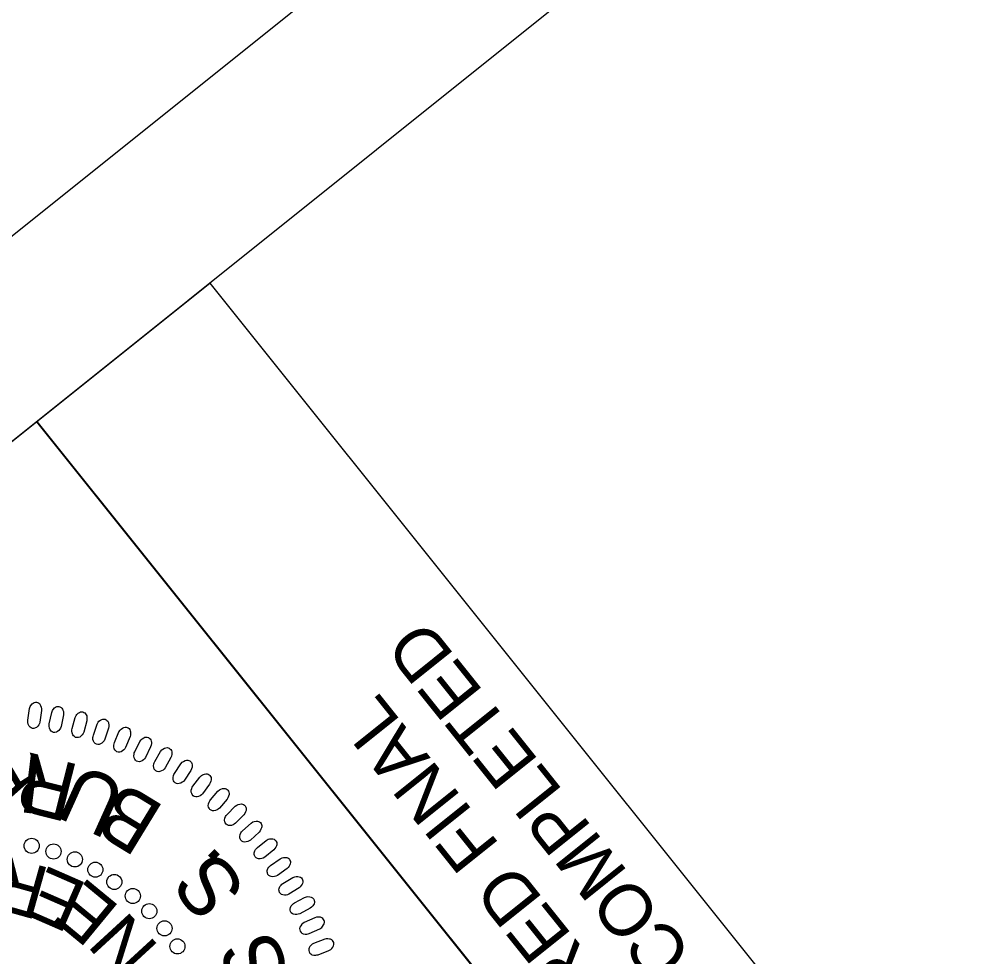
# Model space of a CAD drawing. Extents: x 473437 to 475344, y 504319 to 506318.
# Drawn here: x 473580.9 to 473682.6, y 505671.2 to 505770.6 of the extents above; entities that cross this region are included whole.
import ezdxf

# ---------------------------------------------------------------- set-up
doc = ezdxf.new("R2010")
doc.units = 0
for name, color, linetype in [('Sheet PE Seal Cell', 7, 'Continuous'), ('Sheet Plan CELL', 7, 'Continuous'), ('Sheet Plot Border Outside CELL', 7, 'Continuous'), ('Sheet Sticker Exception Certification CELL', 7, 'Continuous'), ('Sheet Sticker Incomplete CELL', 7, 'Continuous')]:
    doc.layers.add(name, color=color, linetype=linetype)

msp = doc.modelspace()

# ---------------------------------------------------------------- linework, layer by layer
at = {"layer": 'Sheet PE Seal Cell'}
for points in [[(473581.77, 505696.29), (473581.95, 505697.5), (473582.02, 505697.71), (473582.09, 505697.84), (473582.22, 505698), (473582.33, 505698.09), (473582.46, 505698.15), (473582.57, 505698.18), (473582.68, 505698.18), (473582.79, 505698.15), (473582.9, 505698.1), (473583, 505698.03), (473583.09, 505697.91), (473583.13, 505697.82), (473583.18, 505697.67), (473583.21, 505697.48), (473583.21, 505697.32), (473583.04, 505696.07), (473583, 505695.91), (473582.93, 505695.78), (473582.82, 505695.63), (473582.69, 505695.51), (473582.58, 505695.45), (473582.42, 505695.41), (473582.27, 505695.41), (473582.13, 505695.47), (473582.03, 505695.54), (473581.92, 505695.65), (473581.82, 505695.84), (473581.78, 505696.02), (473581.77, 505696.16)], [(473584.05, 505695.89), (473584.3, 505697.09), (473584.38, 505697.3), (473584.46, 505697.42), (473584.6, 505697.57), (473584.72, 505697.65), (473584.85, 505697.71), (473584.96, 505697.73), (473585.07, 505697.72), (473585.18, 505697.68), (473585.29, 505697.63), (473585.38, 505697.55), (473585.46, 505697.43), (473585.5, 505697.34), (473585.54, 505697.18), (473585.56, 505696.99), (473585.55, 505696.83), (473585.3, 505695.6), (473585.25, 505695.44), (473585.17, 505695.31), (473585.05, 505695.17), (473584.92, 505695.06), (473584.8, 505695), (473584.64, 505694.97), (473584.49, 505694.98), (473584.35, 505695.05), (473584.26, 505695.12), (473584.15, 505695.25), (473584.07, 505695.44), (473584.04, 505695.63), (473584.04, 505695.76)], [(473586.46, 505695.38), (473586.79, 505696.56), (473586.88, 505696.76), (473586.97, 505696.89), (473587.12, 505697.02), (473587.25, 505697.1), (473587.37, 505697.15), (473587.49, 505697.16), (473587.6, 505697.15), (473587.7, 505697.1), (473587.81, 505697.04), (473587.9, 505696.95), (473587.97, 505696.83), (473588.01, 505696.73), (473588.03, 505696.57), (473588.04, 505696.38), (473588.02, 505696.22), (473587.7, 505695.01), (473587.63, 505694.85), (473587.55, 505694.73), (473587.42, 505694.6), (473587.28, 505694.49), (473587.16, 505694.44), (473586.99, 505694.43), (473586.84, 505694.45), (473586.71, 505694.53), (473586.62, 505694.6), (473586.53, 505694.73), (473586.46, 505694.93), (473586.44, 505695.12), (473586.44, 505695.25)], [(473588.72, 505694.69), (473589.11, 505695.85), (473589.22, 505696.05), (473589.31, 505696.16), (473589.48, 505696.29), (473589.6, 505696.36), (473589.74, 505696.4), (473589.85, 505696.4), (473589.96, 505696.38), (473590.06, 505696.33), (473590.16, 505696.26), (473590.24, 505696.17), (473590.31, 505696.04), (473590.34, 505695.95), (473590.36, 505695.78), (473590.35, 505695.59), (473590.32, 505695.44), (473589.92, 505694.25), (473589.85, 505694.09), (473589.76, 505693.98), (473589.62, 505693.85), (473589.47, 505693.76), (473589.35, 505693.71), (473589.18, 505693.71), (473589.04, 505693.74), (473588.91, 505693.82), (473588.82, 505693.91), (473588.74, 505694.04), (473588.68, 505694.24), (473588.67, 505694.43), (473588.69, 505694.56)], [(473590.96, 505693.9), (473591.43, 505695.03), (473591.55, 505695.22), (473591.65, 505695.33), (473591.82, 505695.44), (473591.95, 505695.51), (473592.08, 505695.54), (473592.19, 505695.54), (473592.31, 505695.51), (473592.4, 505695.45), (473592.5, 505695.38), (473592.57, 505695.28), (473592.63, 505695.15), (473592.66, 505695.05), (473592.66, 505694.89), (473592.65, 505694.7), (473592.61, 505694.54), (473592.13, 505693.38), (473592.05, 505693.23), (473591.95, 505693.12), (473591.81, 505693.01), (473591.65, 505692.92), (473591.53, 505692.88), (473591.36, 505692.89), (473591.22, 505692.93), (473591.1, 505693.02), (473591.02, 505693.11), (473590.94, 505693.25), (473590.89, 505693.45), (473590.9, 505693.64), (473590.92, 505693.78)], [(473593.1, 505692.92), (473593.64, 505694.03), (473593.77, 505694.21), (473593.88, 505694.31), (473594.06, 505694.41), (473594.19, 505694.47), (473594.33, 505694.49), (473594.44, 505694.48), (473594.55, 505694.45), (473594.64, 505694.38), (473594.73, 505694.3), (473594.8, 505694.2), (473594.85, 505694.06), (473594.87, 505693.97), (473594.87, 505693.8), (473594.84, 505693.62), (473594.79, 505693.46), (473594.24, 505692.33), (473594.15, 505692.19), (473594.05, 505692.08), (473593.89, 505691.98), (473593.73, 505691.9), (473593.61, 505691.87), (473593.44, 505691.89), (473593.3, 505691.94), (473593.18, 505692.04), (473593.11, 505692.13), (473593.04, 505692.28), (473593.01, 505692.48), (473593.03, 505692.67), (473593.06, 505692.8)], [(473595.22, 505691.89), (473595.83, 505692.96), (473595.97, 505693.13), (473596.08, 505693.22), (473596.26, 505693.32), (473596.4, 505693.36), (473596.54, 505693.38), (473596.65, 505693.36), (473596.76, 505693.32), (473596.84, 505693.25), (473596.93, 505693.16), (473596.99, 505693.06), (473597.04, 505692.92), (473597.05, 505692.82), (473597.03, 505692.66), (473596.99, 505692.47), (473596.94, 505692.32), (473596.32, 505691.23), (473596.21, 505691.09), (473596.11, 505690.99), (473595.95, 505690.9), (473595.78, 505690.83), (473595.66, 505690.81), (473595.49, 505690.84), (473595.35, 505690.9), (473595.24, 505691), (473595.18, 505691.1), (473595.12, 505691.25), (473595.1, 505691.45), (473595.13, 505691.65), (473595.17, 505691.77)], [(473597.32, 505690.64), (473597.99, 505691.66), (473598.15, 505691.83), (473598.27, 505691.91), (473598.45, 505691.99), (473598.59, 505692.03), (473598.73, 505692.04), (473598.84, 505692.01), (473598.95, 505691.97), (473599.03, 505691.89), (473599.11, 505691.8), (473599.17, 505691.69), (473599.2, 505691.55), (473599.21, 505691.45), (473599.18, 505691.29), (473599.13, 505691.11), (473599.06, 505690.96), (473598.38, 505689.91), (473598.27, 505689.78), (473598.15, 505689.69), (473597.99, 505689.6), (473597.82, 505689.55), (473597.69, 505689.53), (473597.53, 505689.57), (473597.39, 505689.64), (473597.29, 505689.75), (473597.23, 505689.85), (473597.18, 505690), (473597.17, 505690.21), (473597.22, 505690.4), (473597.26, 505690.52)], [(473599.28, 505689.27), (473600.01, 505690.25), (473600.18, 505690.4), (473600.3, 505690.48), (473600.49, 505690.55), (473600.64, 505690.58), (473600.77, 505690.58), (473600.88, 505690.55), (473600.98, 505690.49), (473601.06, 505690.41), (473601.14, 505690.31), (473601.19, 505690.2), (473601.21, 505690.06), (473601.21, 505689.96), (473601.17, 505689.8), (473601.11, 505689.62), (473601.04, 505689.48), (473600.29, 505688.47), (473600.17, 505688.35), (473600.05, 505688.27), (473599.88, 505688.19), (473599.71, 505688.15), (473599.58, 505688.14), (473599.42, 505688.19), (473599.29, 505688.26), (473599.19, 505688.39), (473599.14, 505688.49), (473599.1, 505688.64), (473599.1, 505688.85), (473599.16, 505689.04), (473599.21, 505689.16)], [(473601.12, 505687.82), (473601.92, 505688.75), (473602.09, 505688.9), (473602.22, 505688.97), (473602.42, 505689.02), (473602.56, 505689.04), (473602.7, 505689.03), (473602.81, 505688.99), (473602.9, 505688.94), (473602.98, 505688.85), (473603.05, 505688.75), (473603.09, 505688.63), (473603.1, 505688.49), (473603.1, 505688.39), (473603.05, 505688.23), (473602.98, 505688.06), (473602.89, 505687.92), (473602.08, 505686.96), (473601.96, 505686.85), (473601.83, 505686.77), (473601.66, 505686.71), (473601.48, 505686.67), (473601.36, 505686.68), (473601.2, 505686.73), (473601.07, 505686.82), (473600.98, 505686.94), (473600.94, 505687.05), (473600.9, 505687.21), (473600.92, 505687.41), (473600.99, 505687.6), (473601.05, 505687.71)], [(473602.89, 505686.27), (473603.75, 505687.15), (473603.93, 505687.28), (473604.06, 505687.35), (473604.26, 505687.39), (473604.41, 505687.4), (473604.54, 505687.38), (473604.64, 505687.33), (473604.74, 505687.27), (473604.8, 505687.18), (473604.87, 505687.07), (473604.9, 505686.96), (473604.91, 505686.81), (473604.9, 505686.71), (473604.84, 505686.56), (473604.76, 505686.39), (473604.66, 505686.26), (473603.79, 505685.35), (473603.66, 505685.25), (473603.53, 505685.18), (473603.35, 505685.13), (473603.18, 505685.1), (473603.05, 505685.11), (473602.9, 505685.18), (473602.78, 505685.27), (473602.7, 505685.4), (473602.66, 505685.51), (473602.63, 505685.67), (473602.67, 505685.88), (473602.74, 505686.05), (473602.81, 505686.17)], [(473604.52, 505684.54), (473605.43, 505685.37), (473605.62, 505685.49), (473605.75, 505685.54), (473605.96, 505685.58), (473606.1, 505685.58), (473606.24, 505685.55), (473606.34, 505685.5), (473606.43, 505685.43), (473606.49, 505685.33), (473606.55, 505685.22), (473606.57, 505685.1), (473606.57, 505684.96), (473606.55, 505684.86), (473606.48, 505684.71), (473606.39, 505684.55), (473606.29, 505684.42), (473605.36, 505683.57), (473605.22, 505683.47), (473605.09, 505683.41), (473604.91, 505683.37), (473604.73, 505683.36), (473604.61, 505683.38), (473604.46, 505683.46), (473604.34, 505683.55), (473604.27, 505683.69), (473604.24, 505683.8), (473604.23, 505683.96), (473604.27, 505684.17), (473604.36, 505684.34), (473604.43, 505684.45)], [(473606.1, 505682.77), (473607.05, 505683.54), (473607.25, 505683.65), (473607.39, 505683.69), (473607.59, 505683.71), (473607.74, 505683.7), (473607.87, 505683.67), (473607.97, 505683.61), (473608.05, 505683.53), (473608.11, 505683.43), (473608.16, 505683.32), (473608.18, 505683.2), (473608.17, 505683.06), (473608.14, 505682.96), (473608.07, 505682.82), (473607.96, 505682.66), (473607.85, 505682.54), (473606.88, 505681.75), (473606.73, 505681.66), (473606.59, 505681.61), (473606.41, 505681.58), (473606.23, 505681.58), (473606.11, 505681.61), (473605.96, 505681.69), (473605.86, 505681.8), (473605.79, 505681.94), (473605.77, 505682.05), (473605.76, 505682.21), (473605.82, 505682.41), (473605.92, 505682.58), (473606, 505682.68)], [(473607.51, 505680.89), (473608.51, 505681.59), (473608.72, 505681.69), (473608.86, 505681.73), (473609.06, 505681.73), (473609.21, 505681.72), (473609.34, 505681.67), (473609.43, 505681.61), (473609.51, 505681.53), (473609.56, 505681.42), (473609.6, 505681.31), (473609.62, 505681.19), (473609.59, 505681.05), (473609.56, 505680.95), (473609.48, 505680.81), (473609.37, 505680.66), (473609.25, 505680.55), (473608.22, 505679.82), (473608.07, 505679.74), (473607.93, 505679.7), (473607.75, 505679.68), (473607.57, 505679.69), (473607.45, 505679.73), (473607.31, 505679.82), (473607.21, 505679.93), (473607.16, 505680.08), (473607.14, 505680.19), (473607.15, 505680.35), (473607.22, 505680.55), (473607.32, 505680.71), (473607.41, 505680.8)], [(473608.8, 505678.96), (473609.85, 505679.6), (473610.06, 505679.68), (473610.2, 505679.71), (473610.41, 505679.7), (473610.55, 505679.68), (473610.68, 505679.62), (473610.77, 505679.55), (473610.84, 505679.47), (473610.88, 505679.36), (473610.92, 505679.24), (473610.92, 505679.12), (473610.89, 505678.98), (473610.86, 505678.89), (473610.76, 505678.75), (473610.64, 505678.61), (473610.52, 505678.51), (473609.45, 505677.85), (473609.29, 505677.78), (473609.15, 505677.74), (473608.97, 505677.73), (473608.79, 505677.76), (473608.67, 505677.8), (473608.54, 505677.9), (473608.44, 505678.02), (473608.4, 505678.17), (473608.39, 505678.28), (473608.41, 505678.44), (473608.49, 505678.63), (473608.61, 505678.78), (473608.7, 505678.88)], [(473610.03, 505676.91), (473611.11, 505677.48), (473611.32, 505677.55), (473611.47, 505677.57), (473611.67, 505677.55), (473611.82, 505677.51), (473611.94, 505677.45), (473612.02, 505677.38), (473612.09, 505677.29), (473612.13, 505677.18), (473612.16, 505677.06), (473612.15, 505676.94), (473612.11, 505676.8), (473612.07, 505676.71), (473611.97, 505676.58), (473611.84, 505676.44), (473611.71, 505676.35), (473610.6, 505675.76), (473610.44, 505675.7), (473610.3, 505675.67), (473610.11, 505675.68), (473609.94, 505675.71), (473609.82, 505675.76), (473609.7, 505675.87), (473609.61, 505675.99), (473609.57, 505676.14), (473609.57, 505676.26), (473609.6, 505676.42), (473609.69, 505676.6), (473609.82, 505676.75), (473609.92, 505676.83)], [(473611.61, 505673.66), (473612.73, 505674.17), (473612.92, 505674.29), (473613.02, 505674.4), (473613.13, 505674.57), (473613.19, 505674.7), (473613.22, 505674.84), (473613.21, 505674.95), (473613.18, 505675.06), (473613.12, 505675.15), (473613.04, 505675.25), (473612.95, 505675.32), (473612.81, 505675.38), (473612.71, 505675.4), (473612.55, 505675.4), (473612.36, 505675.38), (473612.21, 505675.33), (473611.06, 505674.82), (473610.91, 505674.73), (473610.8, 505674.64), (473610.7, 505674.49), (473610.61, 505674.33), (473610.58, 505674.21), (473610.59, 505674.04), (473610.63, 505673.9), (473610.73, 505673.78), (473610.82, 505673.7), (473610.96, 505673.63), (473611.17, 505673.59), (473611.36, 505673.6), (473611.49, 505673.62)], [(473612.55, 505671.42), (473613.69, 505671.86), (473613.89, 505671.97), (473614, 505672.07), (473614.12, 505672.23), (473614.19, 505672.36), (473614.22, 505672.49), (473614.22, 505672.6), (473614.2, 505672.72), (473614.14, 505672.81), (473614.07, 505672.92), (473613.98, 505672.99), (473613.85, 505673.06), (473613.75, 505673.08), (473613.59, 505673.09), (473613.4, 505673.09), (473613.24, 505673.05), (473612.06, 505672.62), (473611.91, 505672.53), (473611.8, 505672.44), (473611.68, 505672.3), (473611.59, 505672.15), (473611.55, 505672.03), (473611.55, 505671.86), (473611.58, 505671.71), (473611.67, 505671.59), (473611.76, 505671.51), (473611.89, 505671.42), (473612.1, 505671.37), (473612.29, 505671.37), (473612.42, 505671.39)]]:
    msp.add_lwpolyline(points, close=True, dxfattribs=at)
for centre in [(473582.18, 505682.96), (473584.5, 505682.36), (473586.76, 505681.52), (473588.93, 505680.43), (473590.94, 505679.13), (473592.9, 505677.64), (473594.65, 505676.03), (473596.26, 505674.21), (473597.63, 505672.3)]:
    msp.add_circle(centre, 0.801, dxfattribs=at)
at = {"layer": 'Sheet Plan CELL'}
for points in [[(473465.55, 505634.17), (474402.85, 504463.03), (475222.63, 505119.12), (474285.35, 506290.25)], [(473557.38, 505579.55), (473494.89, 505657.61), (473582.73, 505727.92), (473645.22, 505649.85)]]:
    msp.add_lwpolyline(points, close=True, dxfattribs=at)
at = {"layer": 'Sheet Plot Border Outside CELL'}
msp.add_lwpolyline([(475344.24, 505003.2), (474292.3, 506317.59), (473437.39, 505633.37), (474489.32, 504318.99)], close=True, dxfattribs=at)
at = {"layer": 'Sheet Sticker Exception Certification CELL'}
for p, q in [((473582.73, 505727.92), (473601.07, 505742.6)), ((473582.73, 505727.92), (473601.07, 505742.6)), ((473601.06, 505742.6), (473726.06, 505586.42)), ((473601.06, 505742.6), (473726.06, 505586.42)), ((473707.71, 505571.73), (473582.72, 505727.91)), ((473707.71, 505571.73), (473582.72, 505727.91))]:
    msp.add_line(p, q, dxfattribs=at)

# ---------------------------------------------------------------- texts
at = {"layer": 'Sheet PE Seal Cell'}
for s, height, rotation, p in [('K', 6.24, 173.0938, (473583.55, 505692.51)), ('R', 6.24, 165.8188, (473587.44, 505691.48)), ('U', 6.24, 155.7189, (473592.59, 505689.32)), ('B', 6.24, 148.6021, (473596.46, 505687.02)), ('.', 6.24, 134.8995, (473602.65, 505681.52)), ('R', 5.67, 164.3348, (473584.3, 505680.53)), ('S', 6.24, 128.0538, (473605.13, 505678.33)), ('E', 5.67, 156.395, (473588.28, 505678.87)), ('E', 5.67, 140.5154, (473591.7, 505676.39)), ('N', 5.67, 132.5756, (473595.82, 505672.2)), ('S', 6.24, 109.4586, (473609.64, 505668.98)), ('46155', 6.236, 128.6526, (473588.84, 505654.88))]:
    msp.add_text(s, height=height, rotation=rotation, dxfattribs=at).set_placement(p)
at = {"layer": 'Sheet Sticker Exception Certification CELL'}
for s, p in [('UNLESS ALL SIGNATURES COMPLETED', (473712.66, 505596.19)), ('UNLESS ALL SIGNATURES COMPLETED', (473712.66, 505596.19)), ('DOCUMENT NOT CONSIDERED FINAL', (473702.62, 505594.65)), ('DOCUMENT NOT CONSIDERED FINAL', (473702.62, 505594.65))]:
    msp.add_text(s, height=5.5, rotation=128.6712, dxfattribs=at).set_placement(p)
at = {"layer": 'Sheet Sticker Incomplete CELL'}
msp.add_text('INCOMPLETE PLANS', height=11.52, rotation=128.6712, dxfattribs=at).set_placement((473632.49, 505556.99))

doc.saveas('drawing.dxf')
